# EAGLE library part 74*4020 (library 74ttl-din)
14-bit asynchronous binary COUNTER
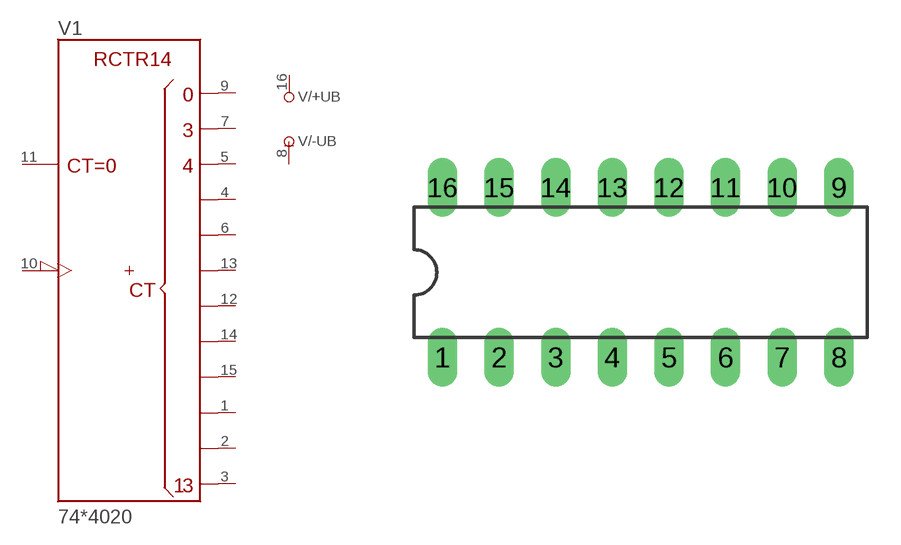
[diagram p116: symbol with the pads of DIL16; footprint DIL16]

Designator prefix V; gates /+UB=+UB /-UB=-UB 1=4020

## 744020N  [DIL16]
1  1:QL  out
2  1:QM  out
3  1:QN  out
4  1:QF  out
5  1:QE  out
6  1:QG  out
7  1:QD  out
8  /-UB:-UB  pwr
9  1:QA  out
10  1:CLK  in
11  1:CLR  in
12  1:QI  out
13  1:QH  out
14  1:QJ  out
15  1:QK  out
16  /+UB:+UB  pwr

## Footprint DIL16 (pad centres in mm)
Dual In Line Package
drill 0.813 long: 1 -8.89,-3.81; 2 -6.35,-3.81; 3 -3.81,-3.81; 4 -1.27,-3.81; 5 1.27,-3.81; 6 3.81,-3.81; 7 6.35,-3.81; 8 8.89,-3.81; 9 8.89,3.81; 10 6.35,3.81; 11 3.81,3.81; 12 1.27,3.81; 13 -1.27,3.81; 14 -3.81,3.81; 15 -6.35,3.81; 16 -8.89,3.81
